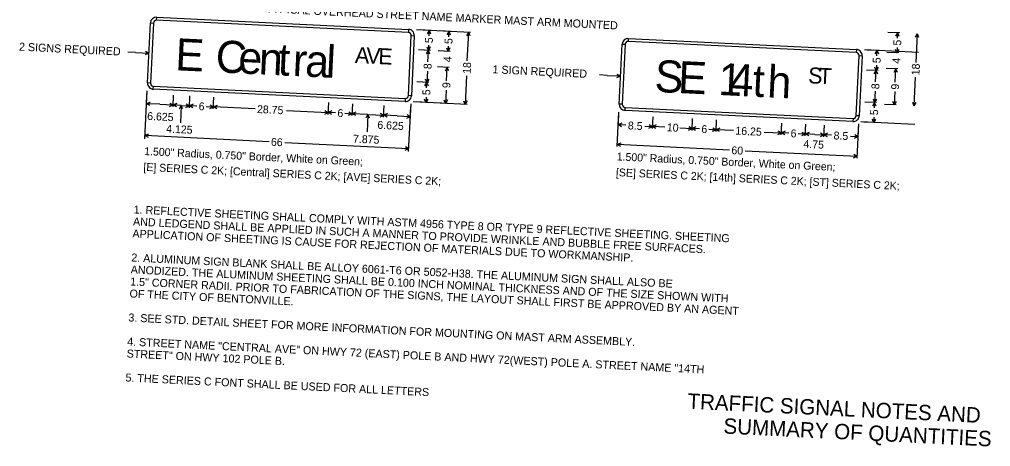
# Model space of a CAD drawing. Extents: x 669100 to 670534, y 743337 to 744379.
# Drawn here: x 669404.3 to 669707.6, y 743337 to 743470.3 of the extents above; entities that cross this region are included whole.
import ezdxf

# ---------------------------------------------------------------- set-up
doc = ezdxf.new("R2010")
doc.units = 0
for name, color, linetype in [('R_Horz Alg Annot', 7, 'Continuous'), ('R_Proposed Road Annot', 7, 'Continuous'), ('rd_ML Pavement Edge_p_n', 7, 'Continuous')]:
    doc.layers.add(name, color=color, linetype=linetype)

msp = doc.modelspace()

# ---------------------------------------------------------------- linework, layer by layer
at = {"layer": 'rd_ML Pavement Edge_p_n'}
for p, q in [((669447.16, 743470.1), (669447.2, 743471.03)), ((669445.24, 743469.25), (669446.17, 743469.21)), ((669525.86, 743467.21), (669525.81, 743466.28)), ((669545.24, 743466.27), (669528.35, 743467.09)), ((669532.95, 743466.87), (669529.27, 743467.05)), ((669531.74, 743465.83), (669532.34, 743466.9)), ((669532.26, 743465.23), (669532.34, 743466.9)), ((669532.84, 743465.77), (669532.34, 743466.9)), ((669526.7, 743465.29), (669527.64, 743465.25)), ((669539.1, 743466.57), (669535.41, 743466.75)), ((669537.88, 743465.53), (669538.48, 743466.6)), ((669538.4, 743464.94), (669538.48, 743466.6)), ((669538.98, 743465.47), (669538.48, 743466.6)), ((669544.02, 743465.23), (669544.63, 743466.3)), ((669544.19, 743457.39), (669544.63, 743466.3)), ((669545.12, 743465.18), (669544.63, 743466.3)), ((669594.48, 743463.47), (669594.53, 743464.41)), ((669679.21, 743466.11), (669675.53, 743466.29)), ((669678, 743465.07), (669678.6, 743466.14)), ((669678.52, 743464.48), (669678.6, 743466.14)), ((669679.1, 743465.02), (669678.6, 743466.14)), ((669684.14, 743464.77), (669684.74, 743465.84)), ((669684.31, 743456.93), (669684.74, 743465.84)), ((669685.24, 743464.72), (669684.74, 743465.84)), ((669532.65, 743460.63), (669528.96, 743460.81)), ((669531.54, 743461.78), (669532.04, 743460.66)), ((669532.12, 743462.32), (669532.04, 743460.66)), ((669532.64, 743461.73), (669532.04, 743460.66)), ((669537.68, 743461.48), (669538.18, 743460.36)), ((669538.26, 743462.02), (669538.18, 743460.36)), ((669538.78, 743461.43), (669538.18, 743460.36)), ((669592.56, 743462.63), (669593.5, 743462.58)), ((669665.69, 743460.95), (669665.65, 743460.01)), ((669685.08, 743460.01), (669668.18, 743460.83)), ((669672.79, 743460.61), (669669.1, 743460.79)), ((669677.8, 743461.02), (669678.3, 743459.9)), ((669678.38, 743461.56), (669678.3, 743459.9)), ((669678.9, 743460.97), (669678.3, 743459.9)), ((669440.62, 743460.03), (669438.22, 743460.15)), ((669440.62, 743460.03), (669444.78, 743459.83)), ((669443.65, 743459.34), (669444.78, 743459.83)), ((669443.71, 743460.43), (669444.78, 743459.83)), ((669531.43, 743459.58), (669532.04, 743460.66)), ((669531.86, 743457.13), (669532.04, 743460.66)), ((669532.53, 743459.53), (669532.04, 743460.66)), ((669538.79, 743460.33), (669535.11, 743460.51)), ((669666.54, 743459.03), (669667.47, 743458.99)), ((669671.57, 743459.56), (669672.17, 743460.64)), ((669672.09, 743458.97), (669672.17, 743460.64)), ((669672.67, 743459.51), (669672.17, 743460.64)), ((669678.91, 743459.87), (669675.23, 743460.05)), ((669538.55, 743455.33), (669534.87, 743455.51)), ((669538.55, 743455.33), (669534.87, 743455.51)), ((669537.34, 743454.29), (669537.94, 743455.36)), ((669537.74, 743451.2), (669537.94, 743455.36)), ((669538.43, 743454.24), (669537.94, 743455.36)), ((669671.38, 743455.52), (669671.87, 743454.39)), ((669671.95, 743456.06), (669671.87, 743454.39)), ((669672.47, 743455.47), (669671.87, 743454.39)), ((669678.67, 743454.87), (669674.98, 743455.05)), ((669678.67, 743454.87), (669674.98, 743455.05)), ((669677.45, 743453.83), (669678.05, 743454.9)), ((669677.85, 743450.74), (669678.05, 743454.9)), ((669678.55, 743453.78), (669678.05, 743454.9)), ((669531.06, 743451.79), (669531.55, 743450.67)), ((669531.72, 743454.2), (669531.55, 743450.67)), ((669532.15, 743451.74), (669531.55, 743450.67)), ((669543.97, 743452.74), (669543.54, 743443.83)), ((669587.84, 743452.88), (669585.44, 743453)), ((669587.84, 743452.88), (669592, 743452.68)), ((669590.88, 743452.19), (669592, 743452.68)), ((669590.93, 743453.29), (669592, 743452.68)), ((669672.49, 743454.36), (669668.8, 743454.54)), ((669671.27, 743453.32), (669671.87, 743454.39)), ((669671.7, 743450.86), (669671.87, 743454.39)), ((669672.37, 743453.27), (669671.87, 743454.39)), ((669684.09, 743452.28), (669683.65, 743443.37)), ((669445.26, 743450.48), (669444.33, 743450.52)), ((669446.11, 743448.56), (669446.16, 743449.5)), ((669532.17, 743450.64), (669528.48, 743450.82)), ((669532.17, 743450.64), (669528.48, 743450.82)), ((669530.95, 743449.6), (669531.55, 743450.67)), ((669531.47, 743449), (669531.55, 743450.67)), ((669532.05, 743449.54), (669531.55, 743450.67)), ((669443.48, 743433.1), (669444.21, 743448.04)), ((669443.98, 743443.43), (669444.16, 743447.11)), ((669452.3, 743443.02), (669452.48, 743446.71)), ((669457.39, 743442.78), (669457.57, 743446.46)), ((669464.88, 743442.41), (669465.06, 743446.1)), ((669524.81, 743445.68), (669524.77, 743444.74)), ((669526.73, 743446.52), (669525.79, 743446.57)), ((669531.33, 743446.09), (669531.25, 743444.43)), ((669537.59, 743448.29), (669537.39, 743444.13)), ((669671.56, 743447.94), (669671.39, 743444.41)), ((669677.71, 743447.83), (669677.51, 743443.67)), ((669445.14, 743444.54), (669444.01, 743444.04)), ((669448.17, 743443.84), (669444.01, 743444.04)), ((669445.09, 743443.44), (669444.01, 743444.04)), ((669448.17, 743443.84), (669452.33, 743443.64)), ((669451.2, 743443.14), (669452.33, 743443.64)), ((669451.26, 743444.24), (669452.33, 743443.64)), ((669453.45, 743444.13), (669452.33, 743443.64)), ((669454.88, 743443.51), (669452.33, 743443.64)), ((669453.4, 743443.04), (669452.33, 743443.64)), ((669454.27, 743442.44), (669454.88, 743443.51)), ((669454.88, 743443.51), (669454.61, 743438.04)), ((669454.88, 743443.51), (669457.42, 743443.39)), ((669455.37, 743442.39), (669454.88, 743443.51)), ((669456.3, 743442.89), (669457.42, 743443.39)), ((669456.35, 743443.99), (669457.42, 743443.39)), ((669458.55, 743443.89), (669457.42, 743443.39)), ((669459.69, 743443.28), (669457.42, 743443.39)), ((669458.49, 743442.79), (669457.42, 743443.39)), ((669462.64, 743443.14), (669464.91, 743443.03)), ((669463.79, 743442.53), (669464.91, 743443.03)), ((669463.84, 743443.63), (669464.91, 743443.03)), ((669466.04, 743443.52), (669464.91, 743443.03)), ((669477.92, 743442.4), (669464.91, 743443.03)), ((669465.99, 743442.42), (669464.91, 743443.03)), ((669500.74, 743440.67), (669500.92, 743444.36)), ((669508.23, 743440.31), (669508.41, 743443.99)), ((669518.07, 743439.83), (669518.25, 743443.52)), ((669518.07, 743439.83), (669518.25, 743443.52)), ((669525.88, 743429.1), (669526.61, 743444.03)), ((669526.39, 743439.43), (669526.57, 743443.11)), ((669544.15, 743443.8), (669527.25, 743444.62)), ((669531.86, 743444.4), (669528.18, 743444.57)), ((669530.75, 743445.55), (669531.25, 743444.43)), ((669531.85, 743445.5), (669531.25, 743444.43)), ((669538.01, 743444.1), (669534.32, 743444.28)), ((669536.9, 743445.25), (669537.39, 743444.13)), ((669537.99, 743445.2), (669537.39, 743444.13)), ((669543.04, 743444.95), (669543.54, 743443.83)), ((669544.14, 743444.9), (669543.54, 743443.83)), ((669592.59, 743443.85), (669591.65, 743443.9)), ((669593.44, 743441.93), (669593.48, 743442.87)), ((669672, 743444.38), (669668.31, 743444.55)), ((669672, 743444.38), (669668.31, 743444.55)), ((669670.78, 743443.33), (669671.39, 743444.41)), ((669670.89, 743445.53), (669671.39, 743444.41)), ((669671.31, 743442.74), (669671.39, 743444.41)), ((669671.99, 743445.48), (669671.39, 743444.41)), ((669671.88, 743443.28), (669671.39, 743444.41)), ((669678.12, 743443.64), (669674.44, 743443.82)), ((669677.01, 743444.79), (669677.51, 743443.67)), ((669678.11, 743444.74), (669677.51, 743443.67)), ((669683.16, 743444.5), (669683.65, 743443.37)), ((669684.26, 743444.44), (669683.65, 743443.37)), ((669487.77, 743441.92), (669500.77, 743441.29)), ((669499.65, 743440.79), (669500.77, 743441.29)), ((669499.7, 743441.89), (669500.77, 743441.29)), ((669501.9, 743441.78), (669500.77, 743441.29)), ((669503.04, 743441.18), (669500.77, 743441.29)), ((669501.84, 743440.68), (669500.77, 743441.29)), ((669505.99, 743441.03), (669508.26, 743440.92)), ((669507.14, 743440.43), (669508.26, 743440.92)), ((669507.19, 743441.52), (669508.26, 743440.92)), ((669509.39, 743441.42), (669508.26, 743440.92)), ((669513.18, 743440.68), (669508.26, 743440.92)), ((669509.33, 743440.32), (669508.26, 743440.92)), ((669512.58, 743439.61), (669513.18, 743440.68)), ((669513.18, 743440.68), (669512.92, 743435.21)), ((669513.18, 743440.68), (669518.1, 743440.44)), ((669513.68, 743439.56), (669513.18, 743440.68)), ((669516.98, 743439.95), (669518.1, 743440.44)), ((669517.03, 743441.05), (669518.1, 743440.44)), ((669519.23, 743440.94), (669518.1, 743440.44)), ((669522.26, 743440.24), (669518.1, 743440.44)), ((669519.17, 743439.84), (669518.1, 743440.44)), ((669522.26, 743440.24), (669526.42, 743440.04)), ((669525.29, 743439.54), (669526.42, 743440.04)), ((669525.34, 743440.64), (669526.42, 743440.04)), ((669591.01, 743430.66), (669591.53, 743441.41)), ((669591.31, 743436.8), (669591.49, 743440.49)), ((669602, 743436.28), (669602.18, 743439.97)), ((669666.57, 743440.26), (669665.63, 743440.3)), ((669671.16, 743439.83), (669671.08, 743438.16)), ((669592.46, 743437.91), (669591.34, 743437.42)), ((669593.74, 743437.3), (669591.34, 743437.42)), ((669592.41, 743436.81), (669591.34, 743437.42)), ((669599.63, 743437.01), (669602.03, 743436.9)), ((669600.9, 743436.4), (669602.03, 743436.9)), ((669600.95, 743437.5), (669602.03, 743436.9)), ((669603.15, 743437.39), (669602.03, 743436.9)), ((669605.9, 743436.71), (669602.03, 743436.9)), ((669603.1, 743436.29), (669602.03, 743436.9)), ((669613.34, 743436.9), (669614.41, 743436.3)), ((669614.38, 743435.68), (669614.56, 743439.37)), ((669615.54, 743436.79), (669614.41, 743436.3)), ((669620.83, 743436.53), (669621.9, 743435.93)), ((669621.87, 743435.32), (669622.05, 743439)), ((669642.25, 743434.33), (669642.43, 743438.01)), ((669649.74, 743433.96), (669649.92, 743437.65)), ((669655.53, 743433.68), (669655.71, 743437.37)), ((669655.53, 743433.68), (669655.71, 743437.37)), ((669664.65, 743439.41), (669664.6, 743438.48)), ((669665.92, 743427.02), (669666.44, 743437.77)), ((669666.22, 743433.16), (669666.4, 743436.85)), ((669683.99, 743437.54), (669667.09, 743438.36)), ((669671.7, 743438.13), (669668.01, 743438.31)), ((669670.59, 743439.29), (669671.08, 743438.16)), ((669671.69, 743439.24), (669671.08, 743438.16)), ((669444.65, 743434.55), (669443.53, 743434.06)), ((669482.27, 743432.18), (669443.53, 743434.06)), ((669444.6, 743433.45), (669443.53, 743434.06)), ((669610.54, 743436.48), (669614.41, 743436.3)), ((669613.29, 743435.8), (669614.41, 743436.3)), ((669616.68, 743436.19), (669614.41, 743436.3)), ((669615.48, 743435.69), (669614.41, 743436.3)), ((669619.63, 743436.04), (669621.9, 743435.93)), ((669620.78, 743435.44), (669621.9, 743435.93)), ((669623.03, 743436.43), (669621.9, 743435.93)), ((669627.3, 743435.67), (669621.9, 743435.93)), ((669622.98, 743435.33), (669621.9, 743435.93)), ((669636.88, 743435.2), (669642.28, 743434.94)), ((669641.15, 743434.45), (669642.28, 743434.94)), ((669641.21, 743435.55), (669642.28, 743434.94)), ((669643.4, 743435.44), (669642.28, 743434.94)), ((669644.55, 743434.83), (669642.28, 743434.94)), ((669643.35, 743434.34), (669642.28, 743434.94)), ((669647.5, 743434.69), (669649.77, 743434.58)), ((669648.64, 743434.08), (669649.77, 743434.58)), ((669648.7, 743435.18), (669649.77, 743434.58)), ((669650.9, 743435.07), (669649.77, 743434.58)), ((669652.67, 743434.44), (669649.77, 743434.58)), ((669650.84, 743433.98), (669649.77, 743434.58)), ((669652.67, 743434.44), (669655.56, 743434.3)), ((669654.44, 743433.8), (669655.56, 743434.3)), ((669654.49, 743434.9), (669655.56, 743434.3)), ((669656.69, 743434.79), (669655.56, 743434.3)), ((669657.96, 743434.18), (669655.56, 743434.3)), ((669656.64, 743433.69), (669655.56, 743434.3)), ((669663.85, 743433.89), (669666.25, 743433.78)), ((669665.13, 743433.28), (669666.25, 743433.78)), ((669665.18, 743434.38), (669666.25, 743433.78)), ((669487.19, 743431.94), (669525.93, 743430.06)), ((669524.86, 743430.66), (669525.93, 743430.06)), ((669592.17, 743431.77), (669591.04, 743431.27)), ((669626.05, 743429.57), (669591.04, 743431.27)), ((669592.11, 743430.67), (669591.04, 743431.27)), ((669524.81, 743429.56), (669525.93, 743430.06)), ((669630.94, 743429.33), (669665.95, 743427.63)), ((669664.83, 743427.14), (669665.95, 743427.63)), ((669664.88, 743428.24), (669665.95, 743427.63))]:
    msp.add_line(p, q, dxfattribs=at)
for points in [[(669525.81, 743466.28), (669447.16, 743470.1), (669447.2, 743471.03), (669525.86, 743467.21), (669525.81, 743466.28)], [(669446.17, 743469.21), (669445.26, 743450.48), (669444.33, 743450.52), (669445.24, 743469.25), (669446.17, 743469.21)], [(669525.79, 743446.57), (669526.7, 743465.29), (669527.64, 743465.25), (669526.73, 743446.52), (669525.79, 743446.57)], [(669665.65, 743460.01), (669594.48, 743463.47), (669594.53, 743464.41), (669665.69, 743460.95), (669665.65, 743460.01)], [(669593.5, 743462.58), (669592.59, 743443.85), (669591.65, 743443.9), (669592.56, 743462.63), (669593.5, 743462.58)], [(669665.63, 743440.3), (669666.54, 743459.03), (669667.47, 743458.99), (669666.57, 743440.26), (669665.63, 743440.3)], [(669446.16, 743449.5), (669524.81, 743445.68), (669524.77, 743444.74), (669446.11, 743448.56), (669446.16, 743449.5)], [(669593.48, 743442.87), (669664.65, 743439.41), (669664.6, 743438.48), (669593.44, 743441.93), (669593.48, 743442.87)]]:
    msp.add_lwpolyline(points, close=True, dxfattribs=at)
for centre, radius, start, end in [((669447.11, 743469.16), 1.88, 87.2201, 177.2198), ((669447.11, 743469.16), 0.938, 87.2201, 177.2198), ((669525.77, 743465.34), 1.88, 357.2199, 87.2201), ((669525.77, 743465.34), 0.938, 357.2199, 87.2201), ((669594.44, 743462.53), 1.88, 87.2201, 177.2198), ((669594.44, 743462.53), 0.938, 87.2201, 177.2198), ((669665.6, 743459.08), 1.88, 357.2199, 87.2201), ((669665.6, 743459.08), 0.938, 357.2199, 87.2201), ((669446.2, 743450.43), 1.88, 177.2198, 267.22), ((669446.2, 743450.43), 0.938, 177.2198, 267.22), ((669524.86, 743446.61), 1.88, 267.22, 357.2202), ((669524.86, 743446.61), 0.938, 267.22, 357.2202), ((669593.53, 743443.81), 1.88, 177.2198, 267.22), ((669593.53, 743443.81), 0.938, 177.2198, 267.22), ((669664.69, 743440.35), 1.88, 267.22, 357.2202), ((669664.69, 743440.35), 0.938, 267.22, 357.2202)]:
    msp.add_arc(centre, radius, start, end, dxfattribs=at)

# ---------------------------------------------------------------- texts
at = {"layer": 'R_Horz Alg Annot'}
for s, p in [('TRAFFIC SIGNAL NOTES AND ', (669612.86, 743348.87)), ('SUMMARY OF QUANTITIES', (669624.1, 743341.12))]:
    msp.add_text(s, height=4.8, rotation=357.2199, dxfattribs=at).set_placement(p)
at = {"layer": 'R_Proposed Road Annot'}
for s, p in [('TYPICAL OVERHEAD STREET NAME MARKER MAST ARM MOUNTED', (669481.29, 743472.53)), ('2 SIGNS REQUIRED', (669404.16, 743460.61)), ('1 SIGN REQUIRED', (669552.03, 743453.55)), ('1. REFLECTIVE SHEETING SHALL COMPLY WITH ASTM 4956 TYPE 8 OR TYPE 9 REFLECTIVE SHEETING. SHEETING ', (669439.95, 743409.81)), ('AND LEDGEND SHALL BE APPLIED IN SUCH A MANNER TO PROVIDE WRINKLE AND BUBBLE FREE SURFACES. ', (669439.77, 743406.06)), ('APPLICATION OF SHEETING IS CAUSE FOR REJECTION OF MATERIALS DUE TO WORKMANSHIP.', (669439.58, 743402.31)), ('2. ALUMINUM SIGN BLANK SHALL BE ALLOY 6061-T6 OR 5052-H38. THE ALUMINUM SIGN SHALL ALSO BE ', (669439.22, 743394.82)), ('ANODIZED. THE ALUMINUM SHEETING SHALL BE 0.100 INCH NOMINAL THICKNESS AND OF THE SIZE SHOWN WITH ', (669439.04, 743391.08)), ('1.5" CORNER RADII. PRIOR TO FABRICATION OF THE SIGNS, THE LAYOUT SHALL FIRST BE APPROVED BY AN AGENT ', (669438.86, 743387.33)), ('OF THE CITY OF BENTONVILLE.', (669438.67, 743383.59)), ('3. SEE STD. DETAIL SHEET FOR MORE INFORMATION FOR MOUNTING ON MAST ARM ASSEMBLY.', (669438.31, 743376.1)), ('4. STREET NAME "CENTRAL AVE" ON HWY 72 (EAST) POLE B AND HWY 72(WEST) POLE A. STREET NAME "14TH ', (669437.95, 743368.6)), ('STREET" ON HWY 102 POLE B.', (669437.77, 743364.86)), ('5. THE SERIES C FONT SHALL BE USED FOR ALL LETTERS', (669437.4, 743357.37))]:
    msp.add_text(s, height=2.5, rotation=357.2199, dxfattribs=at).set_placement(p)
at = {"layer": 'rd_ML Pavement Edge_p_n'}
for s, height, rotation, p in [('E', 10, 357.2199, (669452.86, 743454.49)), ('C', 10, 357.2199, (669465.44, 743453.88)), ('5', 2.46, 87.2201, (669533.38, 743462.87)), ('5', 2.46, 87.2201, (669539.52, 743462.58)), ('5', 2.46, 87.2201, (669679.64, 743462.12)), ('e', 10, 357.2199, (669472.53, 743453.53)), ('n', 10, 357.2199, (669478.92, 743453.22)), ('t', 10, 357.2199, (669484.92, 743452.93)), ('l', 10, 357.2199, (669499.9, 743452.2)), ('A', 5, 357.2199, (669509.03, 743456.77)), ('V', 5, 357.2199, (669512.53, 743456.6)), ('E', 5, 357.2199, (669516.32, 743456.41)), ('r', 10, 357.2199, (669489.51, 743452.71)), ('a', 10, 357.2199, (669493.41, 743452.52)), ('4', 2.46, 87.2201, (669539.24, 743456.92)), ('S', 10, 357.2199, (669602.55, 743447.75)), ('5', 2.46, 87.2201, (669673.21, 743456.61)), ('4', 2.46, 87.2201, (669679.36, 743456.46)), ('8', 2.46, 87.2201, (669532.98, 743454.75)), ('18', 2.461, 87.2201, (669545.23, 743453.29)), ('E', 10, 357.2199, (669609.84, 743447.39)), ('1', 10, 357.2199, (669622.43, 743446.78)), ('4', 10, 357.2199, (669625.93, 743446.61)), ('t', 10, 357.2199, (669633.12, 743446.26)), ('h', 10, 357.2199, (669637.71, 743446.04)), ('S', 5, 357.2199, (669650.54, 743450.42)), ('T', 5, 357.2199, (669653.79, 743450.27)), ('18', 2.461, 87.2201, (669685.35, 743452.84)), ('9', 2.46, 87.2201, (669538.85, 743448.84)), ('8', 2.46, 87.2201, (669672.82, 743448.49)), ('9', 2.46, 87.2201, (669678.97, 743448.38)), ('5', 2.46, 87.2201, (669532.59, 743446.64)), ('6', 2.46, 357.2199, (669460.25, 743442.02)), ('28.75', 2.461, 357.2199, (669478.47, 743441.14)), ('6.625', 2.461, 357.2199, (669444.18, 743438.98)), ('6', 2.46, 357.2199, (669503.59, 743439.92)), ('5', 2.46, 87.2201, (669672.42, 743440.38)), ('4.125', 2.461, 357.2199, (669450.11, 743435.03)), ('6.625', 2.461, 357.2199, (669516.06, 743436.23)), ('8.5', 2.461, 357.2199, (669594.29, 743436.04)), ('10', 2.461, 357.2199, (669606.45, 743435.45)), ('6', 2.46, 357.2199, (669617.24, 743434.93)), ('16.25', 2.461, 357.2199, (669627.86, 743434.41)), ('7.875', 2.461, 357.2199, (669508.46, 743431.91)), ('6', 2.46, 357.2199, (669645.1, 743433.57)), ('8.5', 2.461, 357.2199, (669658.52, 743432.92)), ('66', 2.461, 357.2199, (669482.82, 743430.92)), ('60', 2.461, 357.2199, (669626.61, 743428.31)), ('4.75', 2.461, 357.2199, (669649.1, 743430.3)), ('1.500" Radius, 0.750" Border, White on Green; ', 2.4606, 357.2199, (669443.24, 743428.02)), ('1.500" Radius, 0.750" Border, White on Green; ', 2.4606, 357.2199, (669590.8, 743426.36)), ('[E] SERIES C 2K; [Central] SERIES C 2K; [AVE] SERIES C 2K; ', 2.4606, 357.2199, (669443, 743423.11)), ('[SE] SERIES C 2K; [14th] SERIES C 2K; [ST] SERIES C 2K; ', 2.4606, 357.2199, (669590.56, 743421.44))]:
    msp.add_text(s, height=height, rotation=rotation, dxfattribs=at).set_placement(p)

doc.saveas('drawing.dxf')
